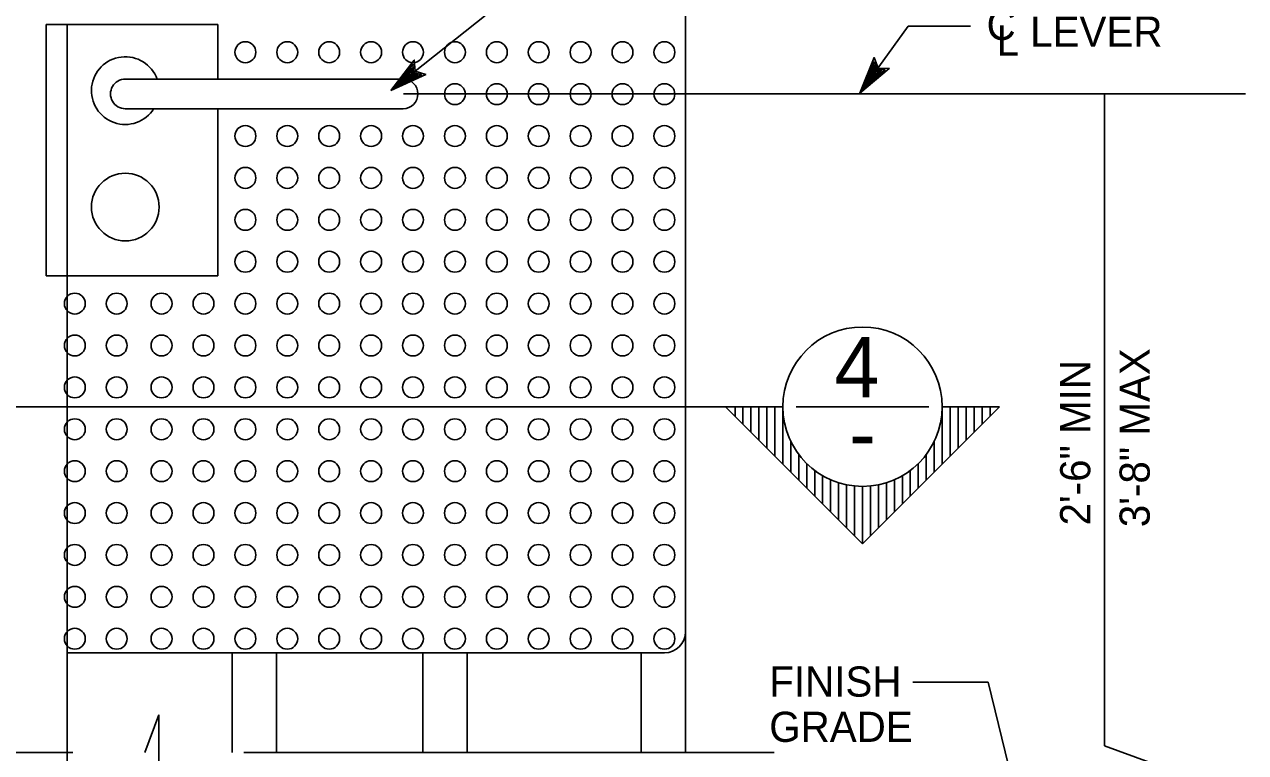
# Model space of a CAD drawing. Extents: x 6710407 to 6714861, y 1868090 to 1871317.
# Drawn here: x 6712653 to 6712895.8, y 1869454.7 to 1869599.6 of the extents above; entities that cross this region are included whole.
import ezdxf

# ---------------------------------------------------------------- set-up
doc = ezdxf.new("R2010")
doc.units = 0
for name, color, linetype in [('G-MARK', 7, 'Continuous'), ('G-TEXT', 7, 'Continuous'), ('Nongeo Data(60)', 7, 'Continuous')]:
    doc.layers.add(name, color=color, linetype=linetype)

msp = doc.modelspace()

# ---------------------------------------------------------------- linework, layer by layer
at = {"layer": 'G-MARK'}
for p, q in [((6712725.83, 1869586.41), (6712820.44, 1869661.56)), ((6712819.11, 1869585.87), (6712828.73, 1869599.19)), ((6712828.73, 1869599.19), (6712841.09, 1869599.19)), ((6712728.33, 1869585.73), (6712895.8, 1869585.73)), ((6712867.73, 1869585.73), (6712867.73, 1869486.5)), ((6712867.73, 1869456.03), (6712867.73, 1869486.5)), ((6712844.63, 1869468.68), (6712829.64, 1869468.68)), ((6712858.43, 1869411.94), (6712844.63, 1869468.68)), ((6712676.93, 1869454.7), (6712679.67, 1869462.23)), ((6712679.67, 1869447.18), (6712679.67, 1869462.23)), ((6712520.13, 1869454.7), (6712662.61, 1869454.7)), ((6712696.62, 1869454.7), (6712802.06, 1869454.7)), ((6712882.78, 1869450.55), (6712867.73, 1869456.03))]:
    msp.add_line(p, q, dxfattribs=at)
at = {"layer": 'G-TEXT'}
for points in [[(6712725.83, 1869586.41), (6712732.78, 1869589.57), (6712730.66, 1869590.26), (6712730.47, 1869592.47), (6712725.83, 1869586.41)], [(6712725.83, 1869586.41), (6712732.78, 1869589.57), (6712730.66, 1869590.26), (6712730.47, 1869592.47), (6712725.83, 1869586.41)], [(6712819.11, 1869585.87), (6712824.95, 1869590.79), (6712822.73, 1869590.88), (6712821.94, 1869592.96), (6712819.11, 1869585.87)], [(6712819.11, 1869585.87), (6712824.95, 1869590.79), (6712822.73, 1869590.88), (6712821.94, 1869592.96), (6712819.11, 1869585.87)], [(6712726.86, 1869587.23), (6712731.9, 1869589.52), (6712730.36, 1869590.01), (6712730.23, 1869591.62), (6712726.86, 1869587.23)], [(6712726.86, 1869587.23), (6712731.9, 1869589.52), (6712730.36, 1869590.01), (6712730.23, 1869591.62), (6712726.86, 1869587.23)], [(6712727.72, 1869587.92), (6712731.16, 1869589.47), (6712730.11, 1869589.81), (6712730.01, 1869590.91), (6712727.72, 1869587.92)], [(6712727.72, 1869587.92), (6712731.16, 1869589.47), (6712730.11, 1869589.81), (6712730.01, 1869590.91), (6712727.72, 1869587.92)], [(6712728.43, 1869588.48), (6712730.55, 1869589.44), (6712729.91, 1869589.65), (6712729.84, 1869590.33), (6712728.43, 1869588.48)], [(6712728.43, 1869588.48), (6712730.55, 1869589.44), (6712729.91, 1869589.65), (6712729.84, 1869590.33), (6712728.43, 1869588.48)], [(6712819.88, 1869586.94), (6712824.11, 1869590.5), (6712822.5, 1869590.56), (6712821.93, 1869592.08), (6712819.88, 1869586.94)], [(6712819.88, 1869586.94), (6712824.11, 1869590.5), (6712822.5, 1869590.56), (6712821.93, 1869592.08), (6712819.88, 1869586.94)], [(6712820.52, 1869587.83), (6712823.41, 1869590.26), (6712822.31, 1869590.3), (6712821.92, 1869591.33), (6712820.52, 1869587.83)], [(6712820.52, 1869587.83), (6712823.41, 1869590.26), (6712822.31, 1869590.3), (6712821.92, 1869591.33), (6712820.52, 1869587.83)], [(6712820.9, 1869588.75), (6712822.21, 1869589.85), (6712821.99, 1869589.86), (6712821.91, 1869590.07), (6712821.28, 1869588.48)], [(6712820.9, 1869588.75), (6712822.21, 1869589.85), (6712821.99, 1869589.86), (6712821.91, 1869590.07), (6712821.28, 1869588.48)], [(6712821.06, 1869588.57), (6712822.84, 1869590.06), (6712822.16, 1869590.09), (6712821.91, 1869590.73), (6712821.06, 1869588.57)], [(6712821.06, 1869588.57), (6712822.84, 1869590.06), (6712822.16, 1869590.09), (6712821.91, 1869590.73), (6712821.06, 1869588.57)], [(6712728.33, 1869588.7), (6712729.89, 1869589.4), (6712729.68, 1869589.48), (6712729.66, 1869589.7), (6712728.62, 1869588.34)], [(6712728.33, 1869588.7), (6712729.89, 1869589.4), (6712729.68, 1869589.48), (6712729.66, 1869589.7), (6712728.62, 1869588.34)]]:
    msp.add_lwpolyline(points, dxfattribs=at)
at = {"layer": 'Nongeo Data(60)'}
for p, q in [((6712784.4, 1869670.58), (6712784.4, 1869478.53)), ((6712691.39, 1869599.55), (6712657.3, 1869599.55)), ((6712657.3, 1869549.55), (6712657.3, 1869599.55)), ((6712661.48, 1869549.03), (6712661.48, 1869599.55)), ((6712691.39, 1869588.66), (6712691.39, 1869599.55)), ((6712728.28, 1869588.66), (6712673.02, 1869588.66)), ((6712728.28, 1869582.79), (6712673.02, 1869582.79)), ((6712691.39, 1869549.55), (6712691.39, 1869582.79)), ((6712691.39, 1869549.55), (6712657.3, 1869549.55)), ((6712661.48, 1869549.03), (6712661.48, 1869446.38)), ((6712792.35, 1869523.51), (6712562.23, 1869523.51)), ((6712803.78, 1869523.51), (6712792.38, 1869523.51)), ((6712819.63, 1869496.26), (6712792.38, 1869523.51)), ((6712794.27, 1869521.63), (6712794.27, 1869523.51)), ((6712795.85, 1869520.04), (6712795.85, 1869523.51)), ((6712797.44, 1869518.46), (6712797.44, 1869523.51)), ((6712799.02, 1869516.87), (6712799.02, 1869523.51)), ((6712800.61, 1869515.29), (6712800.61, 1869523.51)), ((6712802.19, 1869513.7), (6712802.19, 1869523.51)), ((6712803.78, 1869512.12), (6712803.78, 1869523.51)), ((6712832.83, 1869523.51), (6712806.42, 1869523.51)), ((6712819.63, 1869496.26), (6712846.86, 1869523.51)), ((6712835.47, 1869523.51), (6712846.86, 1869523.51)), ((6712835.47, 1869512.12), (6712835.47, 1869523.51)), ((6712837.06, 1869513.7), (6712837.06, 1869523.51)), ((6712838.64, 1869515.29), (6712838.64, 1869523.51)), ((6712840.23, 1869516.87), (6712840.23, 1869523.51)), ((6712841.81, 1869518.46), (6712841.81, 1869523.51)), ((6712843.4, 1869520.04), (6712843.4, 1869523.51)), ((6712844.98, 1869521.63), (6712844.98, 1869523.51)), ((6712805.36, 1869510.53), (6712805.36, 1869516.61)), ((6712833.89, 1869510.53), (6712833.89, 1869516.61)), ((6712806.95, 1869508.95), (6712806.95, 1869514.01)), ((6712832.3, 1869508.94), (6712832.3, 1869514.01)), ((6712808.53, 1869507.36), (6712808.53, 1869512.2)), ((6712810.12, 1869505.78), (6712810.12, 1869510.84)), ((6712829.13, 1869505.77), (6712829.13, 1869510.84)), ((6712830.72, 1869507.36), (6712830.72, 1869512.2)), ((6712811.7, 1869504.19), (6712811.7, 1869509.79)), ((6712813.29, 1869502.61), (6712813.29, 1869508.99)), ((6712814.87, 1869501.03), (6712814.87, 1869508.4)), ((6712816.46, 1869499.44), (6712816.46, 1869507.98)), ((6712818.04, 1869497.86), (6712818.04, 1869507.75)), ((6712819.63, 1869496.27), (6712819.63, 1869507.67)), ((6712821.21, 1869497.84), (6712821.21, 1869507.75)), ((6712822.8, 1869499.43), (6712822.8, 1869507.98)), ((6712824.38, 1869501.01), (6712824.38, 1869508.4)), ((6712825.96, 1869502.6), (6712825.96, 1869508.99)), ((6712827.55, 1869504.19), (6712827.55, 1869509.79)), ((6712784.4, 1869454.7), (6712784.4, 1869478.53)), ((6712661.48, 1869474.55), (6712780.24, 1869474.55)), ((6712694.29, 1869474.55), (6712694.29, 1869454.7)), ((6712703.1, 1869454.7), (6712703.1, 1869474.55)), ((6712732.22, 1869474.55), (6712732.22, 1869454.7)), ((6712741.03, 1869454.7), (6712741.03, 1869474.55)), ((6712775.58, 1869474.55), (6712775.58, 1869454.7))]:
    msp.add_line(p, q, dxfattribs=at)
for centre, radius in [((6712696.9, 1869594.02), 2.08), ((6712705.23, 1869594.02), 2.08), ((6712713.57, 1869594.02), 2.08), ((6712721.9, 1869594.02), 2.08), ((6712730.23, 1869594.02), 2.08), ((6712738.57, 1869594.02), 2.08), ((6712746.9, 1869594.02), 2.08), ((6712755.23, 1869594.02), 2.08), ((6712763.57, 1869594.02), 2.08), ((6712771.9, 1869594.02), 2.08), ((6712780.23, 1869594.02), 2.08), ((6712738.57, 1869585.68), 2.08), ((6712746.9, 1869585.68), 2.08), ((6712755.23, 1869585.68), 2.08), ((6712763.57, 1869585.68), 2.08), ((6712771.9, 1869585.68), 2.08), ((6712780.23, 1869585.68), 2.08), ((6712696.9, 1869577.35), 2.08), ((6712705.23, 1869577.35), 2.08), ((6712713.57, 1869577.35), 2.08), ((6712721.9, 1869577.35), 2.08), ((6712730.23, 1869577.35), 2.08), ((6712738.57, 1869577.35), 2.08), ((6712746.9, 1869577.35), 2.08), ((6712755.23, 1869577.35), 2.08), ((6712763.57, 1869577.35), 2.08), ((6712771.9, 1869577.35), 2.08), ((6712780.23, 1869577.35), 2.08), ((6712696.9, 1869569.02), 2.08), ((6712705.23, 1869569.02), 2.08), ((6712713.57, 1869569.02), 2.08), ((6712721.9, 1869569.02), 2.08), ((6712730.23, 1869569.02), 2.08), ((6712738.57, 1869569.02), 2.08), ((6712746.9, 1869569.02), 2.08), ((6712755.23, 1869569.02), 2.08), ((6712763.57, 1869569.02), 2.08), ((6712771.9, 1869569.02), 2.08), ((6712780.23, 1869569.02), 2.08), ((6712673.02, 1869563.22), 6.73), ((6712696.9, 1869560.68), 2.08), ((6712705.23, 1869560.68), 2.08), ((6712713.57, 1869560.68), 2.08), ((6712721.9, 1869560.68), 2.08), ((6712730.23, 1869560.68), 2.08), ((6712738.57, 1869560.68), 2.08), ((6712746.9, 1869560.68), 2.08), ((6712755.23, 1869560.68), 2.08), ((6712763.57, 1869560.68), 2.08), ((6712771.9, 1869560.68), 2.08), ((6712780.23, 1869560.68), 2.08), ((6712696.9, 1869552.35), 2.08), ((6712705.23, 1869552.35), 2.08), ((6712713.57, 1869552.35), 2.08), ((6712721.9, 1869552.35), 2.08), ((6712730.23, 1869552.35), 2.08), ((6712738.57, 1869552.35), 2.08), ((6712746.9, 1869552.35), 2.08), ((6712755.23, 1869552.35), 2.08), ((6712763.57, 1869552.35), 2.08), ((6712771.9, 1869552.35), 2.08), ((6712780.23, 1869552.35), 2.08), ((6712662.98, 1869544.02), 2.08), ((6712671.31, 1869544.02), 2.08), ((6712680.23, 1869544.02), 2.08), ((6712688.57, 1869544.02), 2.08), ((6712696.9, 1869544.02), 2.08), ((6712705.23, 1869544.02), 2.08), ((6712713.57, 1869544.02), 2.08), ((6712721.9, 1869544.02), 2.08), ((6712730.23, 1869544.02), 2.08), ((6712738.57, 1869544.02), 2.08), ((6712746.9, 1869544.02), 2.08), ((6712755.23, 1869544.02), 2.08), ((6712763.57, 1869544.02), 2.08), ((6712771.9, 1869544.02), 2.08), ((6712780.23, 1869544.02), 2.08), ((6712819.63, 1869523.51), 15.85), ((6712662.98, 1869535.68), 2.08), ((6712671.31, 1869535.68), 2.08), ((6712680.23, 1869535.68), 2.08), ((6712688.57, 1869535.68), 2.08), ((6712696.9, 1869535.68), 2.08), ((6712705.23, 1869535.68), 2.08), ((6712713.57, 1869535.68), 2.08), ((6712721.9, 1869535.68), 2.08), ((6712730.23, 1869535.68), 2.08), ((6712738.57, 1869535.68), 2.08), ((6712746.9, 1869535.68), 2.08), ((6712755.23, 1869535.68), 2.08), ((6712763.57, 1869535.68), 2.08), ((6712771.9, 1869535.68), 2.08), ((6712780.23, 1869535.68), 2.08), ((6712662.98, 1869527.35), 2.08), ((6712671.31, 1869527.35), 2.08), ((6712680.23, 1869527.35), 2.08), ((6712688.57, 1869527.35), 2.08), ((6712696.9, 1869527.35), 2.08), ((6712705.23, 1869527.35), 2.08), ((6712713.57, 1869527.35), 2.08), ((6712721.9, 1869527.35), 2.08), ((6712730.23, 1869527.35), 2.08), ((6712738.57, 1869527.35), 2.08), ((6712746.9, 1869527.35), 2.08), ((6712755.23, 1869527.35), 2.08), ((6712763.57, 1869527.35), 2.08), ((6712771.9, 1869527.35), 2.08), ((6712780.23, 1869527.35), 2.08), ((6712662.98, 1869519.02), 2.08), ((6712671.31, 1869519.02), 2.08), ((6712680.23, 1869519.02), 2.08), ((6712688.57, 1869519.02), 2.08), ((6712696.9, 1869519.02), 2.08), ((6712705.23, 1869519.02), 2.08), ((6712713.57, 1869519.02), 2.08), ((6712721.9, 1869519.02), 2.08), ((6712730.23, 1869519.02), 2.08), ((6712738.57, 1869519.02), 2.08), ((6712746.9, 1869519.02), 2.08), ((6712755.23, 1869519.02), 2.08), ((6712763.57, 1869519.02), 2.08), ((6712771.9, 1869519.02), 2.08), ((6712780.23, 1869519.02), 2.08), ((6712662.98, 1869510.68), 2.08), ((6712671.31, 1869510.68), 2.08), ((6712680.23, 1869510.68), 2.08), ((6712688.57, 1869510.68), 2.08), ((6712696.9, 1869510.68), 2.08), ((6712705.23, 1869510.68), 2.08), ((6712713.57, 1869510.68), 2.08), ((6712721.9, 1869510.68), 2.08), ((6712730.23, 1869510.68), 2.08), ((6712738.57, 1869510.68), 2.08), ((6712746.9, 1869510.68), 2.08), ((6712755.23, 1869510.68), 2.08), ((6712763.57, 1869510.68), 2.08), ((6712771.9, 1869510.68), 2.08), ((6712780.23, 1869510.68), 2.08), ((6712662.98, 1869502.35), 2.08), ((6712671.31, 1869502.35), 2.08), ((6712680.23, 1869502.35), 2.08), ((6712688.57, 1869502.35), 2.08), ((6712696.9, 1869502.35), 2.08), ((6712705.23, 1869502.35), 2.08), ((6712713.57, 1869502.35), 2.08), ((6712721.9, 1869502.35), 2.08), ((6712730.23, 1869502.35), 2.08), ((6712738.57, 1869502.35), 2.08), ((6712746.9, 1869502.35), 2.08), ((6712755.23, 1869502.35), 2.08), ((6712763.57, 1869502.35), 2.08), ((6712771.9, 1869502.35), 2.08), ((6712780.23, 1869502.35), 2.08), ((6712662.98, 1869494.02), 2.08), ((6712671.31, 1869494.02), 2.08), ((6712680.23, 1869494.02), 2.08), ((6712688.57, 1869494.02), 2.08), ((6712696.9, 1869494.02), 2.08), ((6712705.23, 1869494.02), 2.08), ((6712713.57, 1869494.02), 2.08), ((6712721.9, 1869494.02), 2.08), ((6712730.23, 1869494.02), 2.08), ((6712738.57, 1869494.02), 2.08), ((6712746.9, 1869494.02), 2.08), ((6712755.23, 1869494.02), 2.08), ((6712763.57, 1869494.02), 2.08), ((6712771.9, 1869494.02), 2.08), ((6712780.23, 1869494.02), 2.08), ((6712662.98, 1869485.68), 2.08), ((6712671.31, 1869485.68), 2.08), ((6712680.23, 1869485.68), 2.08), ((6712688.57, 1869485.68), 2.08), ((6712696.9, 1869485.68), 2.08), ((6712705.23, 1869485.68), 2.08), ((6712713.57, 1869485.68), 2.08), ((6712721.9, 1869485.68), 2.08), ((6712730.23, 1869485.68), 2.08), ((6712738.57, 1869485.68), 2.08), ((6712746.9, 1869485.68), 2.08), ((6712755.23, 1869485.68), 2.08), ((6712763.57, 1869485.68), 2.08), ((6712771.9, 1869485.68), 2.08), ((6712780.23, 1869485.68), 2.08), ((6712662.98, 1869477.35), 2.08), ((6712671.31, 1869477.35), 2.08), ((6712680.23, 1869477.35), 2.08), ((6712688.57, 1869477.35), 2.08), ((6712696.9, 1869477.35), 2.08), ((6712705.23, 1869477.35), 2.08), ((6712713.57, 1869477.35), 2.08), ((6712721.9, 1869477.35), 2.08), ((6712730.23, 1869477.35), 2.08), ((6712738.57, 1869477.35), 2.08), ((6712746.9, 1869477.35), 2.08), ((6712755.23, 1869477.35), 2.08), ((6712763.57, 1869477.35), 2.08), ((6712771.9, 1869477.35), 2.08), ((6712780.23, 1869477.35), 2.08)]:
    msp.add_circle(centre, radius, dxfattribs=at)
for centre, radius, start, end in [((6712673.02, 1869586.38), 6.73, 19.8308, 327.819), ((6712673.02, 1869585.73), 2.94, 89.9989, 270.0011), ((6712728.28, 1869585.73), 2.94, 270, 90), ((6712780.24, 1869478.72), 4.17, 270, 0)]:
    msp.add_arc(centre, radius, start, end, dxfattribs=at)

# ---------------------------------------------------------------- texts
for s, height, p in [('C', 6, (6712844.3, 1869596.46)), ('LEVER', 6, (6712852.97, 1869595.12)), ('L', 6, (6712846.29, 1869593.34)), ('4', 12, (6712814.06, 1869525.37)), ('-', 12, (6712816.98, 1869512.24)), ('FINISH', 6, (6712801.08, 1869465.83)), ('GRADE', 6, (6712801.08, 1869456.83))]:
    msp.add_text(s, height=height, dxfattribs=at).set_placement(p)
for s, p in [('3\'-8" MAX', (6712876.74, 1869499.54)), ('2\'-6" MIN', (6712864.92, 1869499.88))]:
    msp.add_text(s, height=6, rotation=90, dxfattribs=at).set_placement(p)

doc.saveas('drawing.dxf')
